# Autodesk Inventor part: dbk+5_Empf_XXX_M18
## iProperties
Shininess: 20.0
Length Units: 11269
Angle Units: 11279
Time Units: 11290
Mass Units: 11283
Length Display Precision: 2
Angle Display Precision: 2
Part Number: dbk+5_Empf_XXX_M18
Material: Nichtrostender Stahl - 440C
Document SubType Name: Modellieren
Description: Ipc-25 /CXX/M18
Checked By: Alves
Created: 2005-08
Designer: Ohle
Manufacturer: Standard
Standards Organization: Custom
Density: 0.0
Volumn: 0.0
Area: 0.0
PropertySet Name: Model Information
Control State: 0
Master: False
Checked Out: False
BESTELLNUMMER: Ipc-25 /CXX/M18
ME: ST
Title: Ipc Sensoren
Author: Ohle
Comments: keine Bemerkung
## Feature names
1. Grundkörper [Revolution]
2. Flächenverjüngung1
3. Extrusion10
4. Rundung3 [Fillet]
5. Extrusion11
6. Kabelauslass [Extrusion]
